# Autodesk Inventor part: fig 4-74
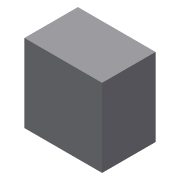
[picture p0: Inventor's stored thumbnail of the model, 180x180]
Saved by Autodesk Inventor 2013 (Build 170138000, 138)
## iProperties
Created: 2012-07
Part Number: fig 4-74
Material: Generic
Document SubType Name: Modeling
Designer: CADCIM
Density: 1 g/cm^3
Author: CADCIM
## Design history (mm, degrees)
sketch "Sketch1"
  geometry: L1 (-7.262, 7.292)-(7.262, 7.292); L2 (7.262, 7.292)-(7.262, -7.292); L3 (7.262, -7.292)-(-7.262, -7.292); L4 (-7.262, -7.292)-(-7.262, 7.292); L5 (-7.262, 7.292)-(7.262, -7.292); L6 (7.262, 7.292)-(-7.262, -7.292); 1 further point
  constraints: 12 end point, 2 midpoint, 2 parallel, 1 horizontal, 1 perpendicular
extrude "Extrusion1" new body sketch "Sketch1" distance "d0" = 10; taper "d1" = 0 deg
body "Solid1"
